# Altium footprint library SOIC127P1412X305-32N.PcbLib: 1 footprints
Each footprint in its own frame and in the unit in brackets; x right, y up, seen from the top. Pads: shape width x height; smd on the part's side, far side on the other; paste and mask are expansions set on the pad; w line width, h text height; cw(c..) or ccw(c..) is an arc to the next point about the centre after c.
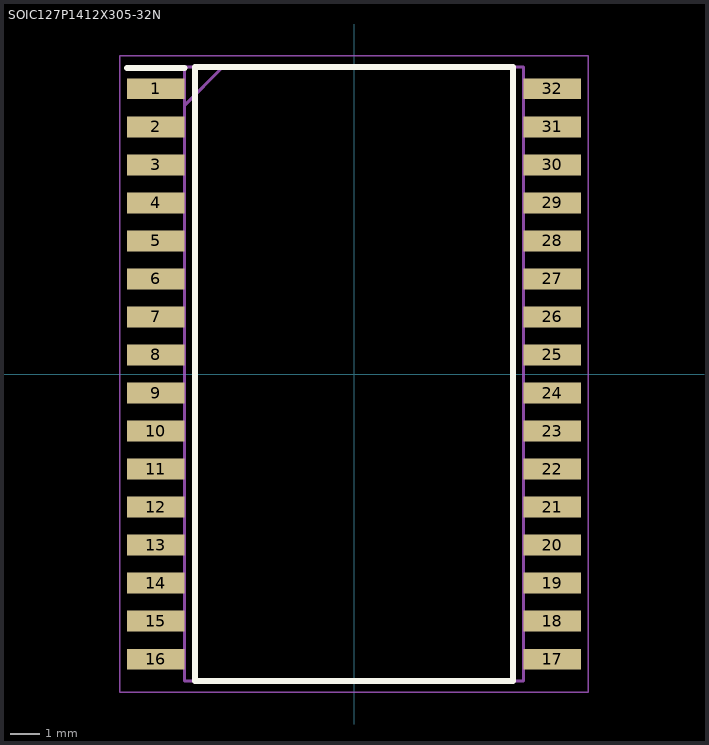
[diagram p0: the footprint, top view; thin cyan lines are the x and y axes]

## SOIC127P1412X305-32N [mm]
pads (32):
  rect 1.922x0.7 smd: 1(-6.614,9.525) 2(-6.614,8.255) 3(-6.614,6.985) 4(-6.614,5.715) 5(-6.614,4.445) 6(-6.614,3.175) 7(-6.614,1.905) 8(-6.614,0.635) 9(-6.614,-0.635) 10(-6.614,-1.905) 11(-6.614,-3.175) 12(-6.614,-4.445) 13(-6.614,-5.715) 14(-6.614,-6.985) 15(-6.614,-8.255) 16(-6.614,-9.525) 17(6.614,-9.525) 18(6.614,-8.255) 19(6.614,-6.985) 20(6.614,-5.715) 21(6.614,-4.445) 22(6.614,-3.175) 23(6.614,-1.905) 24(6.614,-0.635) 25(6.614,0.635) 26(6.614,1.905) 27(6.614,3.175) 28(6.614,4.445) 29(6.614,5.715) 30(6.614,6.985) 31(6.614,8.255) 32(6.614,9.525)
Top Overlay:
  lines w0.2: -7.575,10.225 -5.652,10.225 ; -5.302,-10.248 5.302,-10.248 5.302,10.248 -5.302,10.248 -5.302,-10.248
Mechanical 15:
  lines w0.1: -5.652,8.978 -4.382,10.248 ; -5.652,-10.248 5.652,-10.248 5.652,10.248 -5.652,10.248 -5.652,-10.248
Mechanical 20:
  lines w0.05: -7.825,-10.625 7.825,-10.625 7.825,10.625 -7.825,10.625 -7.825,-10.625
